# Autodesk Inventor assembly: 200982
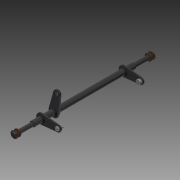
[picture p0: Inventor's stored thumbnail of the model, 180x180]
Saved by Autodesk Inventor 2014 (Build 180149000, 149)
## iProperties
Created: 2007-12
Part Number: 200982
Document SubType Name: Assembly
Designer: MM
Mass: 639.266 g
Surface Area: 331.471 cm^2
Volume: 81.5803 cm^3
Density: 7.83603 g/cm^3
Description: FRONT PIVOT LINK ASSEMBLY
Component Category: Lower Component
Author: MM
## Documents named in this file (5)
- C:\Users\iTools\Desktop\tutorial files\Automotive\2000\200982.iam
- C:\Users\iTools\Desktop\tutorial files\Automotive\2000\208342.iam
- C:\Users\iTools\Desktop\tutorial files\Automotive\8000\800587.ipt
- C:\Users\iTools\Desktop\tutorial files\Automotive\8000\800654.ipt
- C:\Users\iTools\Desktop\tutorial files\Automotive\8000\800391.ipt
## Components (9 placed, 4 different names)
1. 208342:1 [sub-assembly] — Insert:1, Insert:2, Angle:1, Angle:2, Insert:5, Insert:7
2. 800587:1 — Insert:1, Angle:1, Insert:3
3. 800587:2 — Insert:2, Angle:2, Insert:4
4. 800654:1 — Insert:3
5. 800654:2 — Insert:4
6. 800391:1 — Insert:5, Insert:6
7. 800391:2 — Insert:6
8. 800391:3 — Insert:8
9. 800391:4 — Insert:7, Insert:8
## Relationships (10: Insert 8, Angle 2)
- Insert:1: 208342:1 ↔ 800587:1
- Insert:2: 208342:1 ↔ 800587:2
- Angle:1: 208342:1 ↔ 800587:1
- Angle:2: 208342:1 ↔ 800587:2
- Insert:3: 800587:1 ↔ 800654:1
- Insert:4: 800587:2 ↔ 800654:2
- Insert:5: 208342:1 ↔ 800391:1
- Insert:6: 800391:1 ↔ 800391:2
- Insert:7: 208342:1 ↔ 800391:4
- Insert:8: 800391:3 ↔ 800391:4
